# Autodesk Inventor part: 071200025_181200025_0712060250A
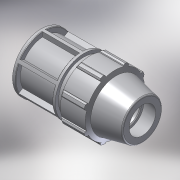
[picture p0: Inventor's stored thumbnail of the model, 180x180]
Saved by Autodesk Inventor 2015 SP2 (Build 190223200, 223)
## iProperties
Created: 2017-02
Part Number: 071200025_181200025_0712060250A
Material: PVC-Piping
Description: PLASSON END PLUG 25
Document SubType Name: Modeling
Designer: KIM
Mass: 92.6774 g
Surface Area: 199.44 cm^2
Volume: 66.1981 cm^3
Density: 1.4 g/cm^3
Appearance: Smooth - White
Author: Кирилл
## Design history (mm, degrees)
derived "07120.ipt"
feature "Solid1::07120.ipt"
tag "TaggingFeature1"
body "Solid1"
other parameters: "d2" = 25, "d4" = 11.71429, "d5" = 20.5, "d7" = 54, "d8" = 40.5, "d9" = 11.71429, "d11" = 2.34286, "d12" = 43.2, "d13" = 120 deg, "d14" = 37.5, "d15" = 12 deg, "d16" = 48.6, "d18" = 1.25, "d19" = 35 deg, "d20" = 17.5 deg, "d21" = 50.22, "d23" = 0, "d25" = 360 deg, "d27" = 1.08, "d34" = 2.7, "d36" = 0, "d42" = 20.5, "d43" = 1.62, "d46" = 0.75, "d53" = 0.5, "d55" = 360 deg, "d59" = 28.7, "d64" = 82, "d66" = 5.4, "d67" = 2.7, "d68" = 77, "d_" = 25, "E_" = 54, "H_" = 82, "l_" = 77
